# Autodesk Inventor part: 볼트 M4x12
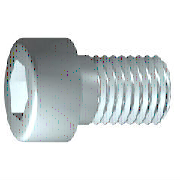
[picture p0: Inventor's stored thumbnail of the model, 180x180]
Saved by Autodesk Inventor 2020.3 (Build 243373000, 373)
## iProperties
IsCustomPart: 0
Created: 2012-02
Part Number: 볼트 M4x12
Material: 강철, 연강
Description: 6각머리 태핑 나사
Document SubType Name: Modeling
Standard: KS B 1003
Designer: mduedu
Standards Organization: KS
Language: ko-KR
Size Designation: M 4 x 12
Categories: <MemberInstance><Categories><Category DisplayName="조임쇠" InternalName="e4da775c-781d-43d5-af7c-5136215cf5a6" Mnemonic="FSTN"><Category DisplayName="볼트" InternalN
Density: 1 g/cm^3
Appearance: 강철
Author: mduedu
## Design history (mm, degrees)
sketch "스케치1"
  geometry: L1 (-1, 0)-(12, 0); L2 (12, 0)-(12, 2); L3 (12, 2)-(1.75, 2); L4 (1.75, 2)-(1.32, 2); L5 (1.32, 2)-(0, 2); L6 (0, 2)-(0, 3.5); L7 (0, 3.5)-(-4, 3.5); L8 (-4, 3.5)-(-4, 1.732); L9 (-4, 1.732)-(-2, 1.732); L10 (-2, 1.732)-(-1, 0); L11 (-7.2, 0)-(15.2, 0) reference; L12 (0, -0.7)-(0, 4.2) reference; L13 (1.75, 2)-(0, 2)
  constraints: 22 end point, 6 parallel, 2 collinear, 2 perpendicular, 1 horizontal, 1 point on line
  dimensions: "d1" = 10.25 distance from line of L3.end L2 (= GEL); "d2" = 0.42952 distance of L4.end L3.end (computed from GAL); "d3" = 4 distance between parallel lines of L8 L6 (= KOH); "d4" = 2 distance of L8.end L9.end (= INTI); "d5" = 60 deg angle of L10 L1; "d6" = 4 diameter of L3 L1 (= GD); "d7" = 4 diameter of L5 L1 (= BDM); "d8" = 3.4641 diameter of L9 L1 (= 1.1547 x SW); "d9" = 7 diameter of L7 L1 (= KOD); "d26" = 12 distance between parallel lines of L12 L2 (= NLG)
revolve "본체" sketch "스케치1" stored, may be unused: angle "d10" = 90 deg
sketch "스케치2"
  geometry: L1 (0, -4.9)-(0, 4.9) reference; L2 (-4.9, 0)-(4.9, 0) reference; L3 (1.732, 0)-(0.866, -1.5); L4 (0.866, -1.5)-(-0.866, -1.5); L5 (-0.866, -1.5)-(-1.732, 0); L6 (-1.732, 0)-(-0.866, 1.5); L7 (-0.866, 1.5)-(0.866, 1.5); L8 (0.866, 1.5)-(1.732, 0); 2 further points
  constraints: 12 end point, 1 coincident, 1 horizontal alignment, 1 point on line, 12 other
extrude "슬롯" join sketch "스케치2" stored distance "d11" = 10; taper "d12" = 0 deg
workplane "Work Plane1"
fillet "Fillet2" dims "d30" = 0.1 (= R)
body "Solid1"
fillet "모깎기1" dims "d17" = 0.4 (= RR)
feature "스레드" dims "d13" = 10.25 (= GEL), "d14" = 0
chamfer "모따기1" distance "d15" = 0.42941 (= -0.5 x SPD + 0.5 x GD); stored, may be unused: second distance "d16" = 0.42941 (= GUL), angle "d27" = 45 deg
other parameters: "GD" = 4 (= NND) [user parameter; used in 2 equation terms], "NLG" = 12 [user parameter; used in 1 equation term], "GEL" = 10.25 [user parameter; used in 2 equation terms], "KOD" = 7 [user parameter; used in 1 equation term], "KOH" = 4 [user parameter; used in 1 equation term], "INTI" = 2 [user parameter; used in 1 equation term], "GAL" = 0.42941 (= 0.61345 x PTC) [user parameter; used in 1 equation term], "GUL" = 0.42941 (= 0.61345 x PTC) [user parameter; used in 1 equation term], "BDM" = 4 (= NND) [user parameter; used in 1 equation term], "SW" = 3 [user parameter; used in 2 equation terms], "RR" = 0.4 [user parameter; used in 1 equation term], "SPD" = 3.14117 (= NND - 1.2269 x PTC) [user parameter; used in 1 equation term], "d19" = 0, "d28" = 0, "d29" = 0, "R" = 0.1 [user parameter; used in 1 equation term], "PHH" = 0.2 [user parameter], "GD1" = 3.14117 (= THREADDIA - 1.2269 x PTC) [user parameter], "THREADDIA" = 4 [user parameter; used in 1 equation term], "FAWI" = 45 deg [user parameter], "TPU" = 14.28571 (computed from PTC) [user parameter], "PTC" = 0.7 [user parameter; used in 5 equation terms], "NND" = 4 [user parameter; used in 3 equation terms], "TOA" = 30 deg [user parameter], "E0" = 3.465 (= 1.155 x SW) [user parameter]
